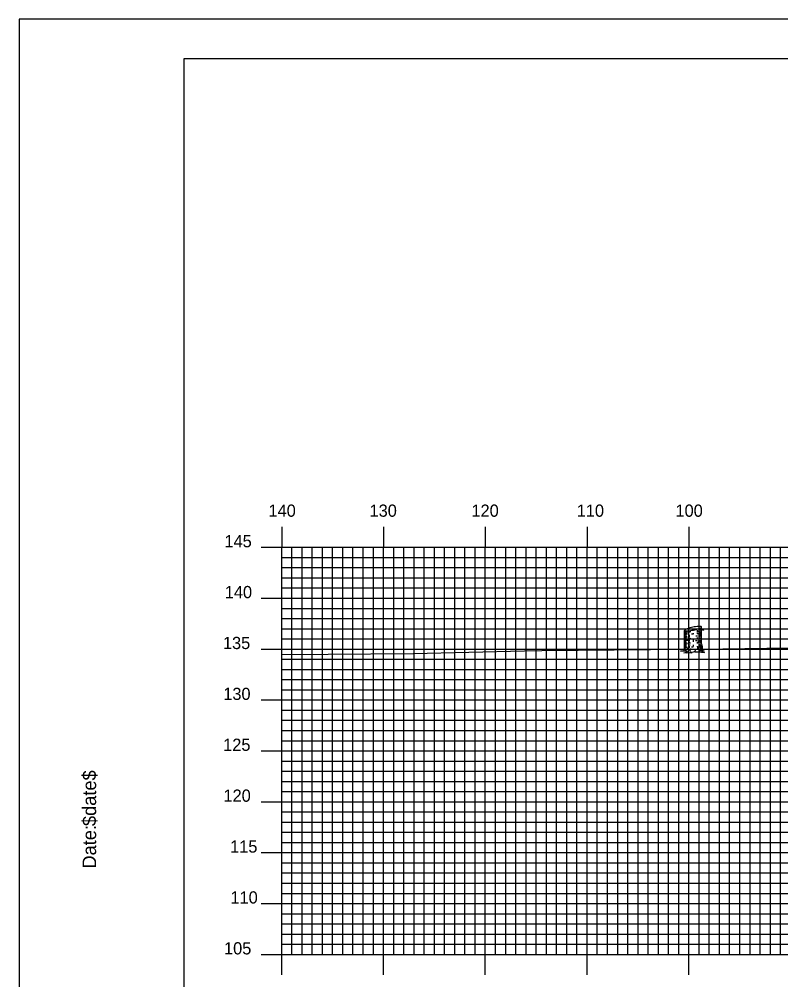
# Model space of a CAD drawing. Extents: x 1768087 to 1768430, y 442591 to 442811.
# Drawn here: x 1768087.2 to 1768162, y 442716.2 to 442810.5 of the extents above; entities that cross this region are included whole.
import ezdxf

# ---------------------------------------------------------------- set-up
doc = ezdxf.new("R2010")
doc.units = 0
for name, color, linetype in [('BORDER', 7, 'Continuous'), ('H_V ANNOTATION', 7, 'Continuous'), ('M_Trees_Conifer_Pay', 7, 'Continuous'), ('MAJOR', 7, 'Continuous'), ('MINOR', 7, 'Continuous'), ('PLOT BOUNDARY', 7, 'Continuous'), ('S_Roadway_Centerline', 7, 'Continuous')]:
    doc.layers.add(name, color=color, linetype=linetype)

msp = doc.modelspace()

# ---------------------------------------------------------------- linework, layer by layer
at = {"layer": 'BORDER'}
msp.add_lwpolyline([(1768103.363, 442596.665), (1768423.363, 442596.665), (1768423.363, 442806.665), (1768103.363, 442806.665)], close=True, dxfattribs=at)
at = {"layer": 'M_Trees_Conifer_Pay'}
for p, q in [((1768154.13, 442750.766), (1768154.13, 442750.603)), ((1768154.202, 442749.191), (1768154.202, 442750.838)), ((1768152.538, 442748.781), (1768152.538, 442750.503)), ((1768152.585, 442750.465), (1768152.585, 442749.994)), ((1768152.585, 442749.93), (1768152.585, 442749.622)), ((1768152.643, 442750.454), (1768152.643, 442750.357)), ((1768152.643, 442750.282), (1768152.643, 442750.078)), ((1768152.643, 442750.021), (1768152.643, 442749.821)), ((1768152.769, 442750.446), (1768152.769, 442750.214)), ((1768152.769, 442750.173), (1768152.769, 442750.099)), ((1768152.988, 442750.467), (1768152.988, 442750.299)), ((1768152.988, 442750.062), (1768152.988, 442749.825)), ((1768153.394, 442750.235), (1768153.394, 442750.14)), ((1768153.784, 442750.509), (1768153.784, 442750.309)), ((1768153.784, 442750.252), (1768153.784, 442750.163)), ((1768153.784, 442749.815), (1768153.784, 442749.71)), ((1768154.013, 442750.705), (1768154.013, 442750.482)), ((1768154.013, 442750.393), (1768154.013, 442750.346)), ((1768154.013, 442750.011), (1768154.013, 442749.879)), ((1768154.07, 442750.21), (1768154.019, 442750.15)), ((1768154.13, 442750.536), (1768154.13, 442750.408)), ((1768154.13, 442750.221), (1768154.13, 442749.885)), ((1768154.13, 442749.848), (1768154.13, 442749.685)), ((1768152.585, 442749.574), (1768152.585, 442749.082)), ((1768152.585, 442749.028), (1768152.585, 442748.781)), ((1768152.643, 442749.774), (1768152.643, 442749.438)), ((1768152.643, 442749.385), (1768152.643, 442749.249)), ((1768152.643, 442749.15), (1768152.643, 442748.771)), ((1768152.769, 442749.696), (1768152.769, 442749.557)), ((1768152.769, 442749.286), (1768152.769, 442749.144)), ((1768152.769, 442748.882), (1768152.769, 442748.788)), ((1768152.988, 442749.58), (1768152.988, 442749.428)), ((1768152.988, 442749.385), (1768152.988, 442749.211)), ((1768152.988, 442748.934), (1768152.988, 442748.781)), ((1768153.394, 442749.622), (1768153.394, 442749.547)), ((1768153.394, 442749.523), (1768153.394, 442749.374)), ((1768153.394, 442749.082), (1768153.394, 442748.929)), ((1768153.784, 442749.343), (1768153.784, 442749.197)), ((1768153.784, 442748.965), (1768153.784, 442748.876)), ((1768154.013, 442749.768), (1768154.013, 442749.658)), ((1768154.013, 442749.523), (1768154.013, 442749.381)), ((1768154.013, 442749.154), (1768154.013, 442748.981)), ((1768154.13, 442749.638), (1768154.13, 442749.421)), ((1768154.13, 442749.391), (1768154.13, 442749.316)), ((1768154.13, 442749.276), (1768154.13, 442749.103)), ((1768152.769, 442748.388), (1768152.931, 442748.452)), ((1768153.206, 442748.324), (1768153.08, 442748.388))]:
    msp.add_line(p, q, dxfattribs=at)
for points in [[(1768152.717, 442749.809), (1768152.711, 442749.904), (1768152.754, 442749.881), (1768152.754, 442749.786)], [(1768153.985, 442750.299), (1768153.954, 442750.214), (1768153.95, 442750.147), (1768153.981, 442750.083)], [(1768154.019, 442750.336), (1768154.055, 442750.262), (1768154.103, 442750.319), (1768154.16, 442750.387), (1768154.253, 442750.581), (1768154.317, 442750.628), (1768154.348, 442750.635)], [(1768154.033, 442750.083), (1768154.07, 442750.21), (1768154.134, 442750.326), (1768154.164, 442750.393), (1768154.233, 442750.54)], [(1768154.248, 442750.569), (1768154.323, 442750.577), (1768154.395, 442750.478)], [(1768154.202, 442749.191), (1768154.253, 442748.929), (1768154.269, 442748.656), (1768154.327, 442748.53), (1768154.463, 442748.5), (1768154.233, 442748.462), (1768154.233, 442748.462), (1768154.238, 442748.415), (1768154.486, 442748.32), (1768154.212, 442748.337), (1768153.856, 442748.357), (1768153.534, 442748.347), (1768153.541, 442748.429), (1768153.393, 442748.347), (1768153.206, 442748.324), (1768153.23, 442748.256), (1768152.962, 442748.299), (1768152.742, 442748.273), (1768152.449, 442748.29), (1768152.738, 442748.347), (1768152.769, 442748.388), (1768152.606, 442748.446), (1768152.369, 442748.456), (1768152.128, 442748.456), (1768152.47, 442748.514), (1768152.511, 442748.594), (1768152.538, 442748.781)], [(1768153.856, 442749.41), (1768153.868, 442749.333), (1768153.916, 442749.343), (1768153.903, 442749.51)], [(1768154.029, 442748.903), (1768154.103, 442748.798), (1768154.107, 442748.625), (1768154.233, 442748.462)], [(1768154.128, 442749.049), (1768154.134, 442748.903), (1768154.181, 442748.835), (1768154.191, 442748.635)], [(1768152.586, 442748.734), (1768152.565, 442748.656), (1768152.544, 442748.561)], [(1768152.664, 442748.713), (1768152.67, 442748.598), (1768152.616, 442748.509), (1768152.606, 442748.446)], [(1768152.826, 442748.74), (1768152.826, 442748.608), (1768152.738, 442748.509)], [(1768153.053, 442748.5), (1768153.12, 442748.594), (1768153.147, 442748.734)], [(1768153.541, 442748.429), (1768153.615, 442748.571), (1768153.625, 442748.672)], [(1768153.792, 442748.798), (1768153.802, 442748.672), (1768153.876, 442748.629)], [(1768154.07, 442748.409), (1768154.055, 442748.547), (1768153.981, 442748.676)]]:
    msp.add_lwpolyline(points, dxfattribs=at)
for centre, radius, start, end in [((1768154.394, 442745.735), 5.179, 101.7194, 108.05939), ((1768154.394, 442745.735), 5.179, 95.37941, 101.7194), ((1768153.983, 442750.093), 0.802, 79.2194, 95.37941), ((1768153.703, 442751.444), 0.802, 288.05939, 304.2194), ((1768154.086, 442750.635), 0.251, 71.05013, 79.2194), ((1768154.013, 442750.988), 0.251, 304.2194, 312.38868), ((1768154.141, 442750.794), 0.0817, 56.7194, 71.05013), ((1768154.127, 442750.864), 0.0817, 312.38868, 326.7194), ((1768154.157, 442750.818), 0.0527, 46.92298, 56.7194), ((1768154.172, 442750.834), 0.0314, 34.2194, 46.92298), ((1768154.151, 442750.848), 0.0527, 326.7194, 336.51582), ((1768154.176, 442750.837), 0.0264, 23.40735, 34.2194), ((1768154.171, 442750.839), 0.0314, 336.51582, 349.2194), ((1768154.179, 442750.838), 0.0226, 11.7194, 23.40735), ((1768154.179, 442750.838), 0.0226, 0.03145, 11.7194), ((1768154.175, 442750.838), 0.0264, 349.2194, 0.03145), ((1768152.57, 442750.325), 0.0334, 163.94846, 180), ((1768152.57, 442750.325), 0.0334, 180, 196.05154), ((1768152.57, 442749.878), 0.0334, 163.94846, 180), ((1768152.57, 442749.878), 0.0334, 180, 196.05154), ((1768152.569, 442750.502), 0.0314, 156.51582, 169.2194), ((1768152.564, 442750.503), 0.0264, 169.2194, 180.03145), ((1768152.56, 442750.503), 0.0226, 180.03145, 191.7194), ((1768152.56, 442750.503), 0.0226, 191.7194, 203.40735), ((1768152.58, 442750.328), 0.0441, 196.05154, 210), ((1768152.58, 442749.881), 0.0441, 196.05154, 210), ((1768152.589, 442750.493), 0.0527, 146.7194, 156.51582), ((1768152.564, 442750.504), 0.0264, 203.40735, 214.2194), ((1768152.568, 442750.507), 0.0314, 214.2194, 226.92298), ((1768152.596, 442750.337), 0.0624, 210, 228.74941), ((1768152.596, 442749.89), 0.0624, 210, 228.74941), ((1768152.613, 442750.477), 0.0817, 132.38868, 146.7194), ((1768152.583, 442750.522), 0.0527, 226.92298, 236.7194), ((1768152.599, 442750.547), 0.0817, 236.7194, 251.05013), ((1768152.668, 442750.419), 0.172, 228.74941, 240), ((1768152.668, 442749.972), 0.172, 228.74941, 240), ((1768152.727, 442750.352), 0.251, 124.2194, 132.38868), ((1768152.653, 442750.706), 0.251, 251.05013, 259.2194), ((1768152.868, 442750.764), 0.571, 240, 240.33672), ((1768152.868, 442750.318), 0.571, 240, 240.33672), ((1768152.869, 442750.553), 0.571, 240, 247.05866), ((1768153.037, 442749.897), 0.802, 108.05939, 124.2194), ((1768152.756, 442751.248), 0.802, 259.2194, 275.37941), ((1768152.868, 442750.764), 0.571, 246.85973, 257.98457), ((1768152.346, 442755.606), 5.179, 275.37941, 281.7194), ((1768153.37, 442754.515), 4.124, 264.6955, 266.73309), ((1768153.369, 442754.282), 4.124, 268.07512, 270), ((1768153.369, 442754.282), 4.124, 270, 270.35814), ((1768152.346, 442755.606), 5.179, 281.7194, 288.05939), ((1768153.37, 442754.071), 4.124, 273.70524, 275.95043), ((1768153.369, 442754.282), 4.124, 275.78493, 277.05584), ((1768153.37, 442754.515), 4.124, 276.23804, 278.1032), ((1768153.871, 442750.997), 0.571, 278.1032, 284.36665), ((1768153.871, 442751.152), 0.571, 284.43166, 292.41325), ((1768153.871, 442750.553), 0.571, 284.44928, 297.04285), ((1768153.871, 442750.997), 0.571, 297.0237, 300), ((1768153.869, 442750.318), 0.571, 297.18959, 300), ((1768154.069, 442749.972), 0.172, 300, 311.25059), ((1768154.07, 442750.807), 0.172, 300, 311.25059), ((1768154.07, 442750.652), 0.172, 300, 311.25059), ((1768154.141, 442749.89), 0.0624, 311.25059, 330), ((1768154.142, 442750.724), 0.0624, 311.25059, 330), ((1768154.142, 442750.57), 0.0624, 311.25059, 330), ((1768154.157, 442749.881), 0.0441, 330, 343.94846), ((1768154.158, 442750.715), 0.0441, 330, 343.94846), ((1768154.158, 442750.56), 0.0441, 330, 343.94846), ((1768154.167, 442749.878), 0.0334, 343.94846, 354.21506), ((1768154.169, 442750.712), 0.0334, 343.94846, 354.21506), ((1768154.169, 442750.557), 0.0334, 343.94846, 354.21506), ((1768154.168, 442750.113), 0.0334, 343.94846, 354.21506), ((1768152.57, 442749.668), 0.0334, 163.94846, 180), ((1768152.57, 442749.668), 0.0334, 180, 196.05154), ((1768152.57, 442749.431), 0.0334, 163.94846, 180), ((1768152.57, 442749.431), 0.0334, 180, 196.05154), ((1768152.57, 442749.233), 0.0334, 163.94846, 180), ((1768152.57, 442749.038), 0.0334, 163.94846, 180), ((1768152.57, 442749.038), 0.0334, 180, 196.05154), ((1768152.58, 442749.671), 0.0441, 196.05154, 210), ((1768152.58, 442749.434), 0.0441, 196.05154, 210), ((1768152.58, 442749.041), 0.0441, 196.05154, 210), ((1768152.596, 442749.68), 0.0624, 210, 228.74941), ((1768152.596, 442749.443), 0.0624, 210, 228.74941), ((1768152.596, 442749.05), 0.0624, 210, 228.74941), ((1768152.668, 442749.762), 0.172, 228.74941, 240), ((1768152.668, 442749.526), 0.172, 228.74941, 240), ((1768152.668, 442749.132), 0.172, 228.74941, 240), ((1768152.868, 442750.108), 0.571, 240, 246.85973), ((1768152.868, 442749.871), 0.571, 240, 246.85973), ((1768152.857, 442749.679), 0.571, 241.23686, 248.02677), ((1768152.868, 442749.477), 0.571, 240, 246.85973), ((1768152.868, 442750.108), 0.571, 259.27072, 261.8968), ((1768153.369, 442753.625), 4.124, 261.8968, 263.14738), ((1768153.369, 442753.191), 4.124, 263.49906, 265.83975), ((1768153.369, 442753.835), 4.124, 264.08098, 266.66759), ((1768153.369, 442753.388), 4.124, 264.71603, 266.31934), ((1768153.369, 442752.995), 4.124, 267.81166, 270), ((1768153.369, 442753.625), 4.124, 270, 270.35814), ((1768153.369, 442752.995), 4.124, 270, 270.13279), ((1768153.369, 442753.625), 4.124, 273.14934, 275.45691), ((1768153.369, 442752.995), 4.124, 275.78493, 276.78961), ((1768153.369, 442753.835), 4.124, 277.61247, 278.1032), ((1768153.869, 442750.318), 0.571, 278.1032, 286.92962), ((1768153.869, 442749.871), 0.571, 285.39827, 297.18959), ((1768153.869, 442749.477), 0.571, 288.50673, 297.27208), ((1768153.869, 442749.673), 0.571, 289.29072, 300), ((1768153.869, 442750.108), 0.571, 297.18959, 300), ((1768154.069, 442749.762), 0.172, 300, 311.25059), ((1768154.069, 442749.328), 0.172, 300, 311.25059), ((1768154.141, 442749.68), 0.0624, 311.25059, 330), ((1768154.141, 442749.245), 0.0624, 311.25059, 330), ((1768154.157, 442749.671), 0.0441, 330, 343.94846), ((1768154.157, 442749.236), 0.0441, 330, 343.94846), ((1768154.167, 442749.668), 0.0334, 343.94846, 354.21506), ((1768154.167, 442749.233), 0.0334, 343.94846, 354.21506), ((1768152.57, 442748.817), 0.0334, 163.94846, 180), ((1768152.57, 442748.817), 0.0334, 180, 196.05154), ((1768152.58, 442748.82), 0.0441, 196.05154, 210), ((1768152.596, 442748.83), 0.0624, 210, 228.74941), ((1768152.668, 442748.912), 0.172, 228.74941, 240), ((1768152.868, 442749.257), 0.571, 240, 244.53138), ((1768153.369, 442752.775), 4.124, 262.44379, 263.51202), ((1768153.369, 442752.775), 4.124, 277.36842, 278.1032), ((1768153.869, 442749.257), 0.571, 278.1032, 281.63703), ((1768154.069, 442748.912), 0.172, 300, 311.25059), ((1768154.141, 442748.83), 0.0624, 311.25059, 330), ((1768154.157, 442748.82), 0.0441, 330, 343.94846), ((1768154.167, 442748.817), 0.0334, 343.94846, 354.21506)]:
    msp.add_arc(centre, radius, start, end, dxfattribs=at)
at = {"layer": 'MAJOR'}
for p, q in [((1768112.963, 442760.669), (1768112.963, 442758.665)), ((1768122.963, 442760.669), (1768122.963, 442758.665)), ((1768132.963, 442760.669), (1768132.963, 442758.665)), ((1768142.963, 442760.669), (1768142.963, 442758.665)), ((1768152.963, 442760.669), (1768152.963, 442758.665)), ((1768110.959, 442758.665), (1768112.963, 442758.665)), ((1768112.963, 442758.665), (1768392.963, 442758.665)), ((1768112.963, 442718.665), (1768112.963, 442758.665)), ((1768112.963, 442718.665), (1768112.963, 442758.665)), ((1768112.963, 442758.665), (1768392.963, 442758.665)), ((1768122.963, 442718.665), (1768122.963, 442758.665)), ((1768132.963, 442718.665), (1768132.963, 442758.665)), ((1768142.963, 442718.665), (1768142.963, 442758.665)), ((1768152.963, 442718.665), (1768152.963, 442758.665)), ((1768110.959, 442753.665), (1768112.963, 442753.665)), ((1768112.963, 442753.665), (1768392.963, 442753.665)), ((1768110.959, 442748.665), (1768112.963, 442748.665)), ((1768112.963, 442748.665), (1768392.963, 442748.665)), ((1768110.959, 442743.665), (1768112.963, 442743.665)), ((1768112.963, 442743.665), (1768392.963, 442743.665)), ((1768110.959, 442738.665), (1768112.963, 442738.665)), ((1768112.963, 442738.665), (1768392.963, 442738.665)), ((1768110.959, 442733.665), (1768112.963, 442733.665)), ((1768112.963, 442733.665), (1768392.963, 442733.665)), ((1768110.959, 442728.665), (1768112.963, 442728.665)), ((1768112.963, 442728.665), (1768392.963, 442728.665)), ((1768110.959, 442723.665), (1768112.963, 442723.665)), ((1768112.963, 442723.665), (1768392.963, 442723.665)), ((1768110.959, 442718.665), (1768112.963, 442718.665)), ((1768112.963, 442718.665), (1768392.963, 442718.665)), ((1768112.963, 442718.665), (1768392.963, 442718.665)), ((1768112.963, 442716.661), (1768112.963, 442718.665)), ((1768122.963, 442716.661), (1768122.963, 442718.665)), ((1768132.963, 442716.661), (1768132.963, 442718.665)), ((1768142.963, 442716.661), (1768142.963, 442718.665)), ((1768152.963, 442716.661), (1768152.963, 442718.665))]:
    msp.add_line(p, q, dxfattribs=at)
at = {"layer": 'MINOR'}
for p, q in [((1768113.963, 442718.665), (1768113.963, 442758.665)), ((1768114.963, 442718.665), (1768114.963, 442758.665)), ((1768115.963, 442718.665), (1768115.963, 442758.665)), ((1768116.963, 442718.665), (1768116.963, 442758.665)), ((1768117.963, 442718.665), (1768117.963, 442758.665)), ((1768118.963, 442718.665), (1768118.963, 442758.665)), ((1768119.963, 442718.665), (1768119.963, 442758.665)), ((1768120.963, 442718.665), (1768120.963, 442758.665)), ((1768121.963, 442718.665), (1768121.963, 442758.665)), ((1768123.963, 442718.665), (1768123.963, 442758.665)), ((1768124.963, 442718.665), (1768124.963, 442758.665)), ((1768125.963, 442718.665), (1768125.963, 442758.665)), ((1768126.963, 442718.665), (1768126.963, 442758.665)), ((1768127.963, 442718.665), (1768127.963, 442758.665)), ((1768128.963, 442718.665), (1768128.963, 442758.665)), ((1768129.963, 442718.665), (1768129.963, 442758.665)), ((1768130.963, 442718.665), (1768130.963, 442758.665)), ((1768131.963, 442718.665), (1768131.963, 442758.665)), ((1768133.963, 442718.665), (1768133.963, 442758.665)), ((1768134.963, 442718.665), (1768134.963, 442758.665)), ((1768135.963, 442718.665), (1768135.963, 442758.665)), ((1768136.963, 442718.665), (1768136.963, 442758.665)), ((1768137.963, 442718.665), (1768137.963, 442758.665)), ((1768138.963, 442718.665), (1768138.963, 442758.665)), ((1768139.963, 442718.665), (1768139.963, 442758.665)), ((1768140.963, 442718.665), (1768140.963, 442758.665)), ((1768141.963, 442718.665), (1768141.963, 442758.665)), ((1768143.963, 442718.665), (1768143.963, 442758.665)), ((1768144.963, 442718.665), (1768144.963, 442758.665)), ((1768145.963, 442718.665), (1768145.963, 442758.665)), ((1768146.963, 442718.665), (1768146.963, 442758.665)), ((1768147.963, 442718.665), (1768147.963, 442758.665)), ((1768148.963, 442718.665), (1768148.963, 442758.665)), ((1768149.963, 442718.665), (1768149.963, 442758.665)), ((1768150.963, 442718.665), (1768150.963, 442758.665)), ((1768151.963, 442718.665), (1768151.963, 442758.665)), ((1768153.963, 442718.665), (1768153.963, 442758.665)), ((1768154.963, 442718.665), (1768154.963, 442758.665)), ((1768155.963, 442718.665), (1768155.963, 442758.665)), ((1768156.963, 442718.665), (1768156.963, 442758.665)), ((1768157.963, 442718.665), (1768157.963, 442758.665)), ((1768158.963, 442718.665), (1768158.963, 442758.665)), ((1768159.963, 442718.665), (1768159.963, 442758.665)), ((1768160.963, 442718.665), (1768160.963, 442758.665)), ((1768161.963, 442718.665), (1768161.963, 442758.665)), ((1768112.963, 442757.665), (1768392.963, 442757.665)), ((1768112.963, 442757.665), (1768114.967, 442757.665)), ((1768112.963, 442756.665), (1768392.963, 442756.665)), ((1768112.963, 442756.665), (1768114.967, 442756.665)), ((1768112.963, 442755.665), (1768392.963, 442755.665)), ((1768112.963, 442755.665), (1768114.967, 442755.665)), ((1768112.963, 442754.665), (1768392.963, 442754.665)), ((1768112.963, 442754.665), (1768114.967, 442754.665)), ((1768112.963, 442752.665), (1768392.963, 442752.665)), ((1768112.963, 442752.665), (1768114.967, 442752.665)), ((1768112.963, 442751.665), (1768392.963, 442751.665)), ((1768112.963, 442751.665), (1768114.967, 442751.665)), ((1768112.963, 442750.665), (1768392.963, 442750.665)), ((1768112.963, 442750.665), (1768114.967, 442750.665)), ((1768112.963, 442749.665), (1768392.963, 442749.665)), ((1768112.963, 442749.665), (1768114.967, 442749.665)), ((1768112.963, 442747.665), (1768392.963, 442747.665)), ((1768112.963, 442747.665), (1768114.967, 442747.665)), ((1768112.963, 442746.665), (1768392.963, 442746.665)), ((1768112.963, 442746.665), (1768114.967, 442746.665)), ((1768112.963, 442745.665), (1768392.963, 442745.665)), ((1768112.963, 442745.665), (1768114.967, 442745.665)), ((1768112.963, 442744.665), (1768392.963, 442744.665)), ((1768112.963, 442744.665), (1768114.967, 442744.665)), ((1768112.963, 442742.665), (1768392.963, 442742.665)), ((1768112.963, 442742.665), (1768114.967, 442742.665)), ((1768112.963, 442741.665), (1768392.963, 442741.665)), ((1768112.963, 442741.665), (1768114.967, 442741.665)), ((1768112.963, 442740.665), (1768392.963, 442740.665)), ((1768112.963, 442740.665), (1768114.967, 442740.665)), ((1768112.963, 442739.665), (1768392.963, 442739.665)), ((1768112.963, 442739.665), (1768114.967, 442739.665)), ((1768112.963, 442737.665), (1768392.963, 442737.665)), ((1768112.963, 442737.665), (1768114.967, 442737.665)), ((1768112.963, 442736.665), (1768392.963, 442736.665)), ((1768112.963, 442736.665), (1768114.967, 442736.665)), ((1768112.963, 442735.665), (1768392.963, 442735.665)), ((1768112.963, 442735.665), (1768114.967, 442735.665)), ((1768112.963, 442734.665), (1768392.963, 442734.665)), ((1768112.963, 442734.665), (1768114.967, 442734.665)), ((1768112.963, 442732.665), (1768392.963, 442732.665)), ((1768112.963, 442732.665), (1768114.967, 442732.665)), ((1768112.963, 442731.665), (1768392.963, 442731.665)), ((1768112.963, 442731.665), (1768114.967, 442731.665)), ((1768112.963, 442730.665), (1768392.963, 442730.665)), ((1768112.963, 442730.665), (1768114.967, 442730.665)), ((1768112.963, 442729.665), (1768392.963, 442729.665)), ((1768112.963, 442729.665), (1768114.967, 442729.665)), ((1768112.963, 442727.665), (1768392.963, 442727.665)), ((1768112.963, 442727.665), (1768114.967, 442727.665)), ((1768112.963, 442726.665), (1768392.963, 442726.665)), ((1768112.963, 442726.665), (1768114.967, 442726.665)), ((1768112.963, 442725.665), (1768392.963, 442725.665)), ((1768112.963, 442725.665), (1768114.967, 442725.665)), ((1768112.963, 442724.665), (1768392.963, 442724.665)), ((1768112.963, 442724.665), (1768114.967, 442724.665)), ((1768112.963, 442722.665), (1768392.963, 442722.665)), ((1768112.963, 442722.665), (1768114.967, 442722.665)), ((1768112.963, 442721.665), (1768392.963, 442721.665)), ((1768112.963, 442721.665), (1768114.967, 442721.665)), ((1768112.963, 442720.665), (1768392.963, 442720.665)), ((1768112.963, 442720.665), (1768114.967, 442720.665)), ((1768112.963, 442719.665), (1768392.963, 442719.665)), ((1768112.963, 442719.665), (1768114.967, 442719.665))]:
    msp.add_line(p, q, dxfattribs=at)
at = {"layer": 'PLOT BOUNDARY'}
msp.add_lwpolyline([(1768087.176, 442590.547), (1768427.176, 442590.547), (1768427.176, 442810.547), (1768087.176, 442810.547)], close=True, dxfattribs=at)
at = {"layer": 'S_Roadway_Centerline'}
msp.add_lwpolyline([(1768112.963, 442748.13), (1768117.535, 442748.177), (1768125.886, 442748.227), (1768136.796, 442748.487), (1768138.529, 442748.521), (1768156.3, 442748.686), (1768162.761, 442748.783)], dxfattribs=at)

# ---------------------------------------------------------------- texts
at = {"layer": 'BORDER'}
for s, p in [('$date$', (1768094.732, 442731.275)), ('Date:', (1768094.732, 442727.099))]:
    msp.add_text(s, height=1.3392, rotation=90, dxfattribs=at).set_placement(p)
at = {"layer": 'H_V ANNOTATION'}
for s, p in [('140', (1768111.667, 442761.665)), ('130', (1768121.593, 442761.665)), ('120', (1768131.603, 442761.665)), ('110', (1768141.946, 442761.665)), ('100', (1768151.646, 442761.665)), ('145', (1768107.34, 442758.665)), ('140', (1768107.372, 442753.665)), ('135', (1768107.19, 442748.665)), ('130', (1768107.222, 442743.665)), ('125', (1768107.212, 442738.665)), ('120', (1768107.244, 442733.665)), ('115', (1768107.897, 442728.665)), ('110', (1768107.929, 442723.665)), ('105', (1768107.297, 442718.665))]:
    msp.add_text(s, height=1.2, dxfattribs=at).set_placement(p)
at = {"layer": 'MAJOR'}
msp.add_text('-', height=0.012, dxfattribs=at).set_placement((1768112.954, 442718.665))

doc.saveas('drawing.dxf')
